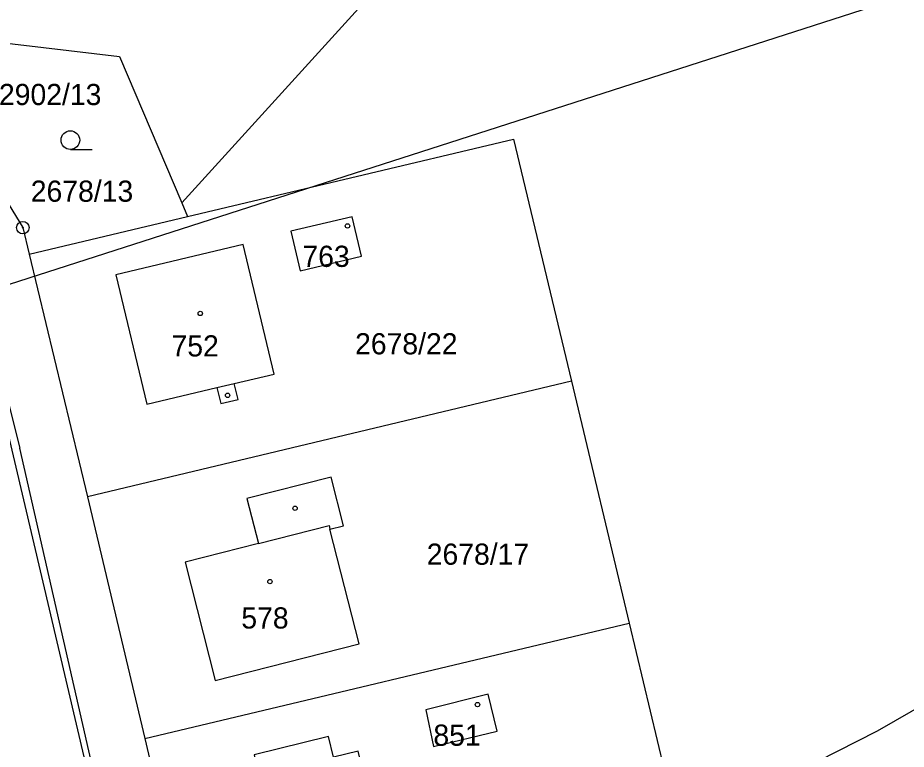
# Model space of a CAD drawing. Extents: x -758836 to -757729, y -1175316 to -1174366.
# Drawn here: x -758356 to -758284.7, y -1174928.9 to -1174870.2 of the extents above; entities that cross this region are included whole.
import ezdxf

# ---------------------------------------------------------------- set-up
doc = ezdxf.new("R2010")
doc.units = 0
for name, color, linetype in [('_NOR-pomocná', 7, 'Continuous'), ('Hranice parcel', 7, 'Continuous'), ('Parcelní čísla', 7, 'Continuous'), ('Vnitřní kresba', 7, 'Continuous'), ('Značky bodu BP', 7, 'Continuous'), ('Značky budov', 7, 'Continuous'), ('Značky kultur', 7, 'Continuous')]:
    doc.layers.add(name, color=color, linetype=linetype)

msp = doc.modelspace()

# ---------------------------------------------------------------- linework, layer by layer
at = {"layer": '_NOR-pomocná'}
msp.add_lwpolyline([(-758417.595, -1174755.224), (-758317.652, -1174723.031), (-758272.123, -1174864.38), (-758372.066, -1174896.572)], close=True, dxfattribs=at)
at = {"layer": 'Hranice parcel'}
for p, q in [((-758310.72, -1174849.73), (-758342.82, -1174885.08)), ((-758342.82, -1174885.08), (-758342.36, -1174886.17)), ((-758355.06, -1174889.19), (-758342.36, -1174886.17)), ((-758355.06, -1174889.19), (-758350.37, -1174908.66)), ((-758311.55, -1174899.38), (-758350.37, -1174908.66)), ((-758311.55, -1174899.38), (-758306.92, -1174918.8)), ((-758350.37, -1174908.66), (-758345.78, -1174928.06)), ((-758345.78, -1174928.06), (-758306.92, -1174918.8)), ((-758306.92, -1174918.8), (-758302.92, -1174935.57)), ((-758345.78, -1174928.06), (-758341.26, -1174947.41))]:
    msp.add_line(p, q, dxfattribs=at)
for points in [[(-758362.51, -1174871.59), (-758347.81, -1174873.33), (-758342.82, -1174885.08)], [(-758342.36, -1174886.17), (-758316.19, -1174879.95), (-758311.55, -1174899.38)], [(-758359.63, -1174880.45), (-758355.57, -1174887.06), (-758355.06, -1174889.19)], [(-758297.139, -1175157.069), (-758301.82, -1175137.17), (-758334.58, -1174998.03), (-758360.35, -1174888.27), (-758361.81, -1174882.07)], [(-758302.92, -1174935.57), (-758286.99, -1174927.44), (-758267.9, -1174916.47), (-758249.14, -1174905.98), (-758236.24, -1174897.16), (-758223.14, -1174884.37)], [(-758333.32, -1174890.52), (-758328.39, -1174889.35), (-758329.14, -1174886.18), (-758334.07, -1174887.35), (-758333.32, -1174890.52)], [(-758345.61, -1174901.23), (-758340, -1174899.9), (-758339.69, -1174901.18), (-758338.3, -1174900.85), (-758338.6, -1174899.57), (-758335.39, -1174898.81), (-758337.88, -1174888.4), (-758348.1, -1174890.84), (-758345.61, -1174901.23)], [(-758336.66, -1174912.42), (-758342.55, -1174913.91), (-758340.14, -1174923.41), (-758328.59, -1174920.48), (-758330.93, -1174911.26), (-758329.84, -1174910.99), (-758330.83, -1174907.09), (-758337.58, -1174908.8), (-758336.66, -1174912.42)], [(-758318.24, -1174924.5), (-758323.22, -1174925.76), (-758322.61, -1174928.72), (-758317.51, -1174927.47), (-758318.24, -1174924.5)], [(-758326.1, -1174939.86), (-758328.65, -1174929.09), (-758330.65, -1174929.56), (-758331.04, -1174927.9), (-758337.01, -1174929.38), (-758336.63, -1174930.98), (-758338.22, -1174931.36), (-758335.63, -1174942.14), (-758326.1, -1174939.86)]]:
    msp.add_lwpolyline(points, dxfattribs=at)
at = {"layer": 'Vnitřní kresba'}
for p, q in [((-758358.45, -1174894.31), (-758355.8, -1174904.75)), ((-758340, -1174899.9), (-758338.6, -1174899.57)), ((-758334.58, -1174998.03), (-758355.8, -1174904.75)), ((-758336.66, -1174912.42), (-758331, -1174910.98)), ((-758331, -1174910.98), (-758330.93, -1174911.26))]:
    msp.add_line(p, q, dxfattribs=at)
at = {"layer": 'Značky bodu BP'}
for radius in [0.5, 0.0303]:
    msp.add_circle((-758355.57, -1174887.06), radius, dxfattribs=at)
at = {"layer": 'Značky budov'}
for centre in [(-758329.517, -1174886.919), (-758341.327, -1174893.949), (-758339.137, -1174900.519), (-758333.727, -1174909.589), (-758335.737, -1174915.469), (-758319.087, -1174925.349)]:
    msp.add_circle(centre, 0.175, dxfattribs=at)
at = {"layer": 'Značky kultur'}
msp.add_line((-758351.753, -1174880.78), (-758350.003, -1174880.78), dxfattribs=at)
msp.add_circle((-758351.753, -1174880.03), 0.75, dxfattribs=at)

# ---------------------------------------------------------------- texts
at = {"layer": 'Parcelní čísla'}
for s, p in [('2902/13', (-758357.48, -1174877.22)), ('2678/13', (-758354.928, -1174884.98)), ('763', (-758333.134, -1174890.21)), ('752', (-758343.634, -1174897.4)), ('2678/22', (-758328.908, -1174897.23)), ('2678/17', (-758323.158, -1174914.12)), ('578', (-758338.034, -1174919.24)), ('851', (-758322.624, -1174928.65))]:
    msp.add_text(s, height=1.7, dxfattribs=at).set_placement(p)

doc.saveas('drawing.dxf')
